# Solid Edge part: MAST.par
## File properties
Author: ke06
Template: Normal.par
Last saved by: Andris
Revision: 12
Application: Solid Edge
Accuracy: 0,990
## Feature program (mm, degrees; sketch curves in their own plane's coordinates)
sketch for "unnamed Protrusion 1" plane through (0, 0, -7.9568) normal (0, 0, 1) x-axis (1, 0, 0)
extrude "unnamed Protrusion 1" add finite 350 along +normal
sketch for "ExtrudedProtrusion_11" plane through (0, 0, 0) normal (1, 0, 0) x-axis (0, 1, 0)
extrude "ExtrudedProtrusion_11" add finite 150.7001 along +normal
fillet "Round_4" radius 5
sketch for "ExtrudedCutout_1" plane through (0, 0, 0) normal (1, 0, 0) x-axis (0, 1, 0)
  line (-2.4199, 334.0645) -> (-2.4199, 68.3576)
  line (-2.4199, 68.3576) -> (-2.4199, 62.065)
  line (-2.4199, 62.065) -> (2.5801, 62.065)
  line (2.5801, 62.065) -> (2.5801, 68.3576)
  line (2.5801, 68.3576) -> (2.4199, 334.0645)
  line (-2.4199, 334.0645) -> (2.4199, 334.0645)
extrude "ExtrudedCutout_1" cut finite 158.4565 along +normal
sketch for "ExtrudedCutout_2" plane through (0, 0, -7.9568) normal (0, 0, 1) x-axis (1, 0, 0)
  circle centre (0, 0) radius 5
extrude "ExtrudedCutout_2" cut finite 20.3947 along +normal
sketch used by "ExtrudedProtrusion_12" plane through (0, 0, 334.0645) normal (0, 0, 1) x-axis (1, 0, 0)
extrude "ExtrudedProtrusion_12" add finite 19.2375 along +normal
sketch used by "ExtrudedProtrusion_14" plane through (0, 0, 0) normal (0, -1, 0) x-axis (1, 0, 0)
extrude "ExtrudedProtrusion_14" add finite 1 symmetric
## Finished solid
Body 1: solid body, 18 faces, 36 edges, 22 vertices, 2 separate solids.
  Faces by surface: plane 11, cylinder 3, sphere 2, swept 2
  Edges by curve: line 19, circle 9, ellipse 4, spline 4
Bounding box of the edges (mm; curved faces can reach further): 155.331 x 10.000 x 340.933, from (-5, -5, 12.4379) to (150.3309, 5, 353.3711).
Cylindrical faces by radius (mm): R1.4676 x1, R5 x2
Spherical faces by radius (mm): R5 x2
Planar faces by outward normal: +x 1, +y 2, +z 2, -x 1, -y 3, -z 2
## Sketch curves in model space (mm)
circle centre (0, 0, 334.0645) radius 1.4676
spline (1.9896, 0, 342.3427) -> (35.0798, 0, 340.3705) -> (65.9074, 0, 352.359)
spline (1.9896, 0, 353.302) -> (33.6232, 0, 349.1689) -> (65.9074, 0, 352.359)
line (1.9896, 0, 353.302) -> (1.9896, 0, 342.3427)
line (0, 2.5801, 68.3576) -> (0, 2.4199, 334.0645)
line (0, 2.5801, 62.065) -> (0, 2.5801, 68.3576)
line (0, -2.4199, 62.065) -> (0, 2.5801, 62.065)
line (0, -2.4199, 68.3576) -> (0, -2.4199, 62.065)
line (0, -2.4199, 334.0645) -> (0, -2.4199, 68.3576)
line (0, -2.4199, 334.0645) -> (0, 2.4199, 334.0645)
circle centre (0, 0, 60.1795) radius 5
circle centre (0, 0, -7.9568) radius 5
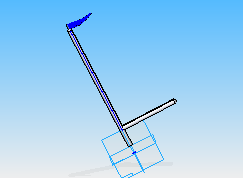
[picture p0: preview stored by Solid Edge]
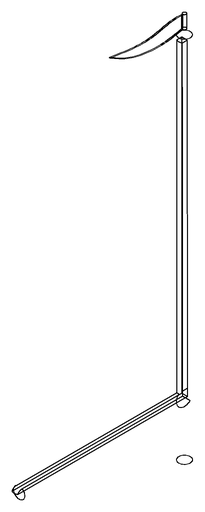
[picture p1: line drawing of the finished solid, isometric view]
